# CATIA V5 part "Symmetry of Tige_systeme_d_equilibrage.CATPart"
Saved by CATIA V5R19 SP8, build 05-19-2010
Part number: Symmetry of Tige_systeme_d_equilibrage
Bounding box of the stored display mesh (mm): x -142 to -79.944, y -42.638 to 547.188, z 1182.598 to 1300.066
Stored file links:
  G:\EU_thinkMotion\CFAO_2010\MMS_groupe2\MMS_groupe2\OK\nrosalie\nrosalie_cfao_support_d_arme_legere_final\Symmetry of Tige_systeme_d_equilibrage.CATPart
  G:\EU_thinkMotion\CFAO_2010\MMS_groupe2\MMS_groupe2\OK\nrosalie\nrosalie_cfao_support_d_arme_legere_final\Tige_systeme_d_equilibrage.CATPart
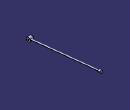
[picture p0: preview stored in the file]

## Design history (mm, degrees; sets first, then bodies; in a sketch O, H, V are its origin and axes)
Body1 (main body)
  Body2 "Corps du corps principal d'origine"
    Solid1: linked copy from another document
  Assemble1: tool Body2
